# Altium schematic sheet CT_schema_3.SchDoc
size 245 x 144 mm
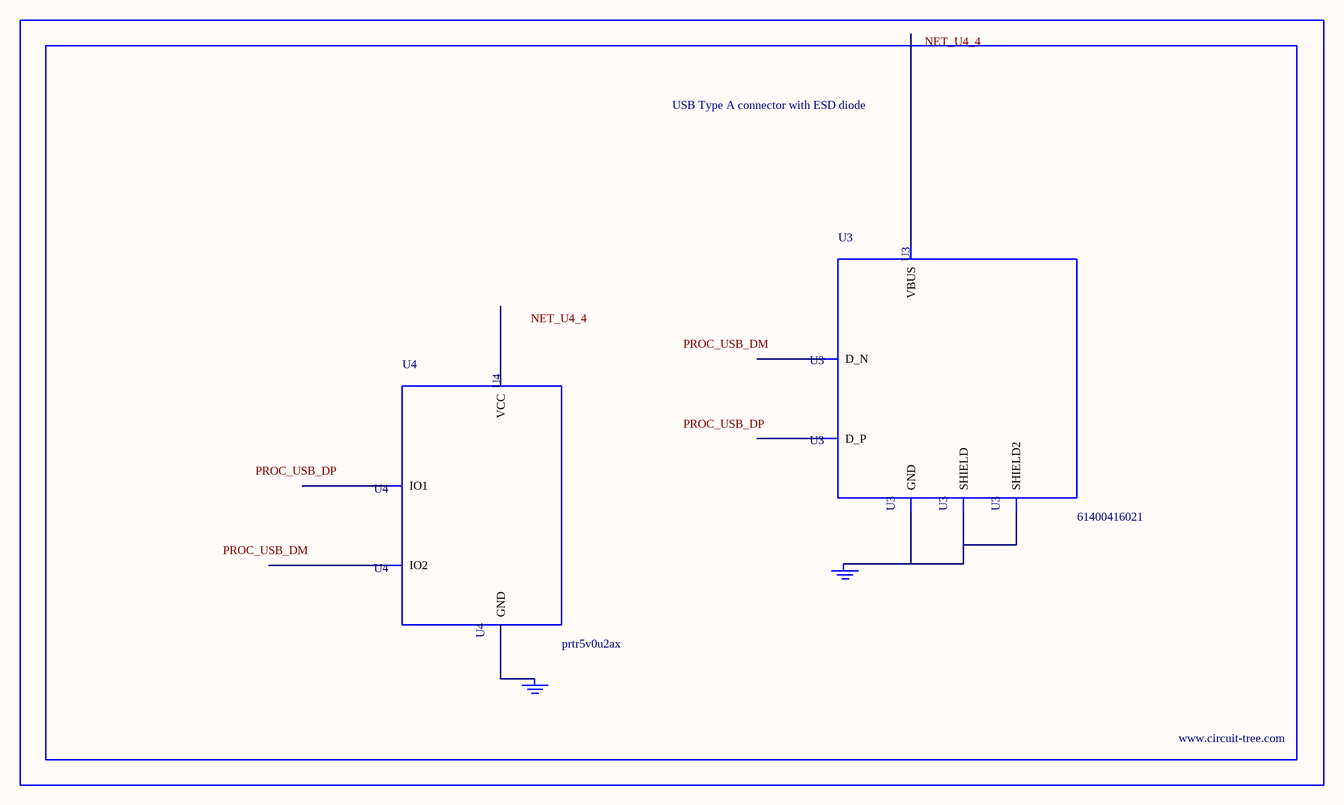
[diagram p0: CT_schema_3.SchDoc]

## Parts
BORDER2  (no value)
GND_INSTANCE_2_0  (no value)
GND_INSTANCE_2_1  (no value)
U3  61400416021  [USB-A-H]
U4  prtr5v0u2ax  [SOT143B]

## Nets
NetGND_INSTANCE_2_0_0: GND_INSTANCE_2_0.0(GND) U3.4(GND) U3.5(SHIELD) U3.6(SHIELD2)
NetGND_INSTANCE_2_1_0: GND_INSTANCE_2_1.0(GND) U4.1(GND)

Not connected (* = marked no-connect by the designer): U3 1(VBUS) 2(D_N) 3(D_P); U4 2(IO1) 3(IO2) 4(VCC)

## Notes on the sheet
- Labels drawn without touching a wire or pin: NET_U4_4, PROC_USB_DM, PROC_USB_DP

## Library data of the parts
BORDER2 = BORDER_PAGE2
GND_INSTANCE_2_0 GND_INSTANCE_2_1 = GND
